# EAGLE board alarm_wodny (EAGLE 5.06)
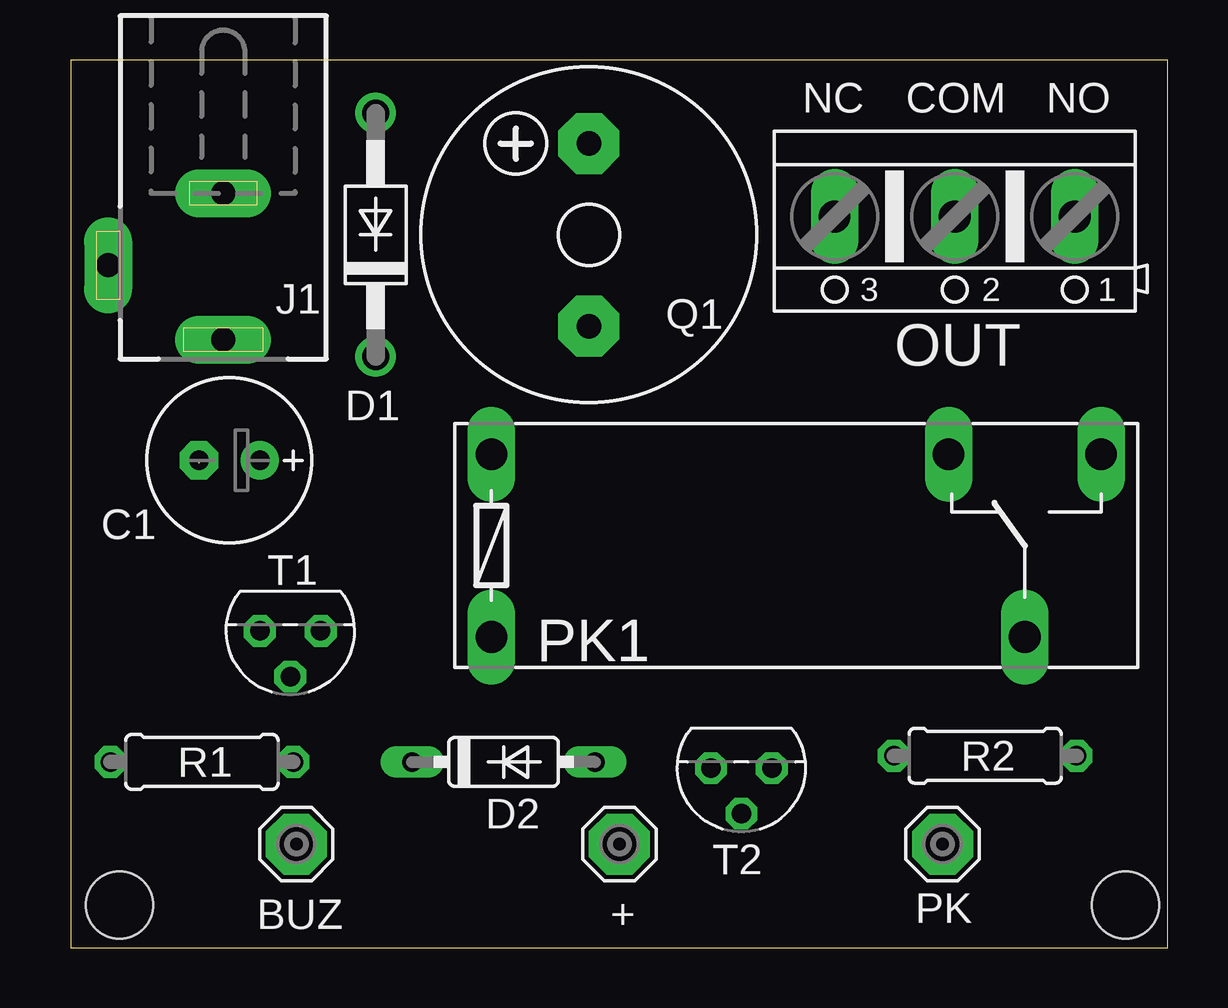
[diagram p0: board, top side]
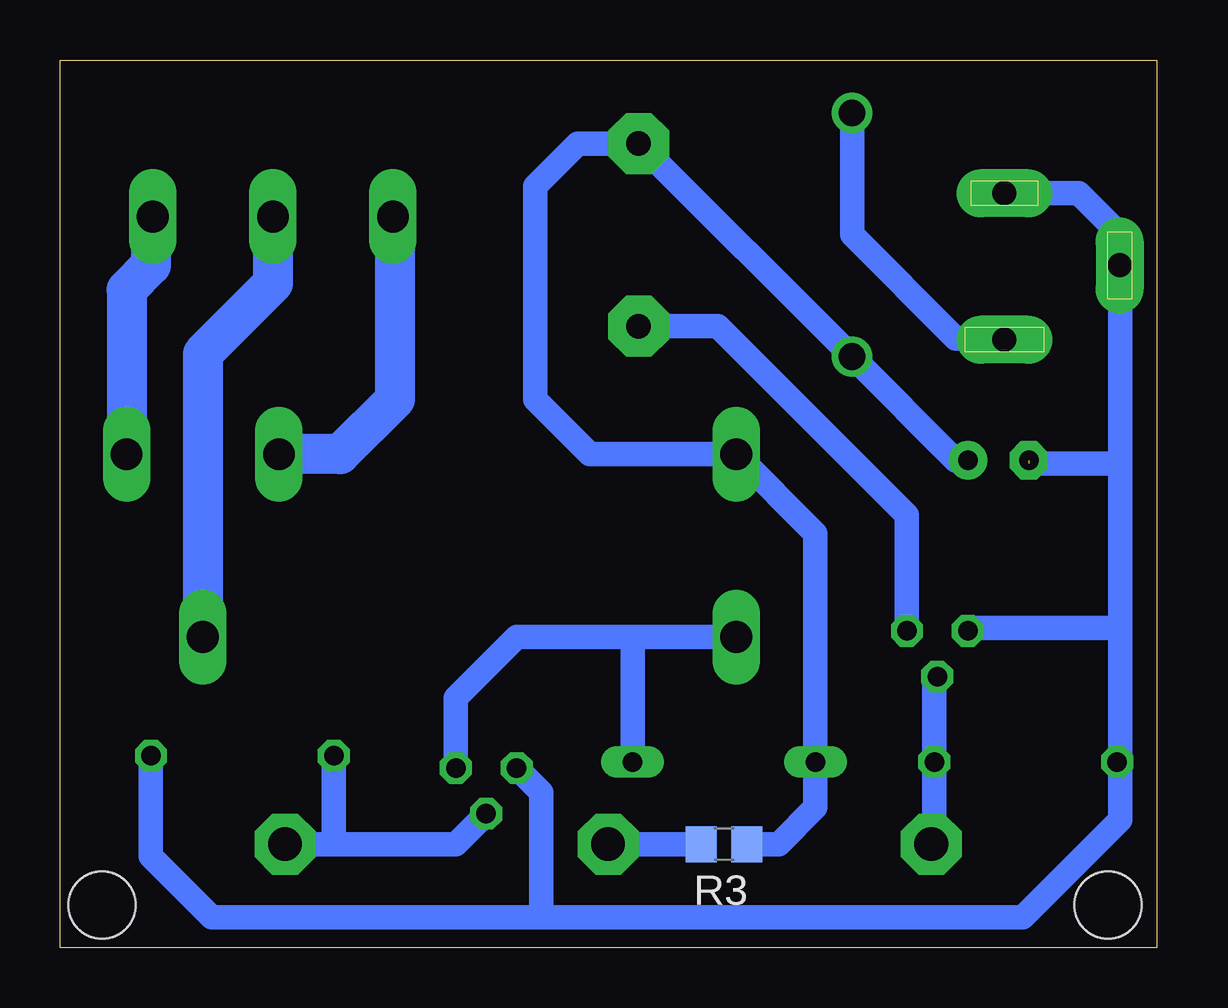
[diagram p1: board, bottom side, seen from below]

Size 45.7 x 37.01 mm. Coordinates in mm from the lower left corner, seen from the top.
Outline: 0,0 45.7,0 45.7,37.01 0,37.01 0,0
Copper layers (1*16): Top 0.035mm / dielectric 1.5mm / Bottom 0.035mm
Design rules "default": minimum track width 10mil, minimum drill 24mil, track to track 8mil, track to pad 8mil, pad to pad 8mil, via to via 8mil, smd to smd 8mil, copper to edge 40mil, drill to drill 8mil, minimum pad ring 10mil, minimum via ring 8mil, stop-mask expansion 4mil, vias tented up to drill 0mil, thermal gap 10mil
Holes 2.8 mm at 2.03,1.78 43.94,1.78

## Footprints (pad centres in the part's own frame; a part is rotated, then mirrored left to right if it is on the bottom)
SE14 = drill 1.397 pad 2.54 octagon: MP 0,0
E2,5-7 = drill 0.813 pad 1.6 round: + -1.27,0 | drill 0.813 pad 1.6 octagon: - 1.27,0
DO41-10 = drill 1.118 round: A 5.08,0; C -5.08,0
DO35-7 = drill 0.813 long: A 3.81,0; C -3.81,0
DCJ0202 = drill 1 pad 2 long: 1 0,3.1; 2 4.8,0; 3 0,-3
AK500/3 = drill 1.321 long: 1 -5.004,0; 2 0,0; 3 5.004,0
G6RW = drill 1.321 long: 1 -12.7,-3.81; 2 -12.7,3.81; O 6.35,3.81; P 9.525,-3.81; S 12.7,3.81
F/CM12P = drill 1.016 pad 2.54 octagon: + 3.81,0; - -3.81,0
0207/7 = drill 0.813 octagon: 1 -3.81,0; 2 3.81,0
C0805 = smd 1.3 x 1.5: 1 -0.95,0; 2 0.95,0
TO92 = drill 0.813 octagon: 1 1.27,0; 2 0,1.905; 3 -1.27,0

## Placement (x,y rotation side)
+  SE14  [SE14]  22.86,4.32 0 top
BUZ  SE14  [SE14]  9.4,4.32 0 top
C1  [E2,5-7]  6.6,20.32 180 top
D1  1N4004  [DO41-10]  12.7,29.72 90 top
D2  1N4148DO35-7  [DO35-7]  18.03,7.75 0 top
J1  DCJ0202  [DCJ0202]  6.35,28.45 180 top
OUT  [AK500/3]  36.83,30.48 180 top
PK  SE14  [SE14]  36.32,4.32 0 top
PK1  G6RW  [G6RW]  30.23,16.76 0 top
Q1  F/CM12P  [F/CM12P]  21.59,29.72 90 top
R1  [0207/7]  5.46,7.75 0 top
R2  [0207/7]  38.1,8 180 top
R3  [C0805]  18.03,4.32 0 bottom
T1  BC517  [TO92]  9.14,13.21 180 top
T2  BC517  [TO92]  27.94,7.49 180 top

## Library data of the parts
+ BUZ PK = solpad
C1 R1-R3 = rcl
D1 D2 = diode
J1 = con-jack
OUT = con-ptr500
PK1 = relay
Q1 = buzzer
T1 T2 = transistor-npn

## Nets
N$1: D1.A J1.1
N$2: C1.+ D1.C D2.C PK1.2 Q1.+
N$3: C1.- J1.3 R1.1 R2.1 T1.1 T2.1
N$4: BUZ.MP R1.2 T1.2
N$5: PK.MP R2.2 T2.2
N$6: Q1.- T1.3
N$7: OUT.2 PK1.P
N$8: D2.A PK1.1 T2.3
N$11: OUT.3 PK1.O
N$12: OUT.1 PK1.S
S$1: +.MP

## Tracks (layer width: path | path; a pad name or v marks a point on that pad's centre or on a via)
N$1
  Bottom 1.016: J1.1 6.4,25.4 | 6.4,25.4 6.35,25.4 | 6.4,25.4 8.38,25.4 12.7,29.72 D1.A
N$2
  Bottom 1.016: C1.+ 8.38,20.32 D1.C Q1.+ 24.13,33.53 25.91,31.75 25.91,22.86 23.62,20.57 PK1.2 14.22,17.27 D2.C 14.22,5.84 15.75,4.32 17.02,4.32
N$3  (1 unrouted)
  Bottom 1.016: 1.52,13.34 1.52,20.19 | 1.52,20.19 5.33,20.19 | T1.1 7.62,13.34 1.52,13.34 | R2.1 41.91,3.81 39.37,1.27 25.65,1.27 | 25.65,1.27 5.59,1.27 1.52,5.33 1.52,12.7 | T2.1 25.65,6.48 25.65,1.27 | 1.52,12.7 1.52,13.34 | R1.1 1.52,7.87 1.52,12.7 | 1.52,20.19 1.52,29.72 3.25,31.45 J1.3
N$4
  Bottom 1.016: T1.2 9.27,10.92 9.27,7.37 | BUZ.MP 9.27,4.45 9.27,7.37 | 9.27,7.37 R1.2
N$5
  Bottom 1.016: T2.2 29.21,4.32 34.29,4.32 | 34.29,4.32 R2.2 | 34.29,4.32 PK.MP
N$6
  Bottom 1.016: Q1.- 18.29,25.91 10.41,18.03 T1.3
N$7
  Bottom 1.676: OUT.2 36.83,27.69 39.75,24.77 PK1.P
N$8
  Bottom 1.016: 21.84,12.95 26.67,12.95 29.21,10.41 T2.3 | PK1.1 21.84,12.95 | 21.84,12.95 D2.A
N$11
  Bottom 1.676: OUT.3 31.75,30.4 31.75,22.86 34.04,20.57 PK1.O
N$12
  Bottom 1.676: OUT.1 41.91,30.4 41.91,28.45 42.93,27.43 PK1.S
S$1
  Bottom 1.016: 19.05,4.32 +.MP

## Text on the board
tNames: NC | COM | NO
